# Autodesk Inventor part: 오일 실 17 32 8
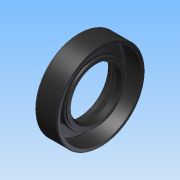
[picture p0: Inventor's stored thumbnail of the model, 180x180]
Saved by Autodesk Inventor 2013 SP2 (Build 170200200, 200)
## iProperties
Created: 2025-05
Part Number: 오일 실 17 32 8
Material: Generic
Document SubType Name: Modeling
Designer: a
Density: 1 g/cm^3
Author: a
변환 표준: STEP AP214IS
전처리기: Build: 200, Release: 2013 SP2 Update 6 - Date: Thu 07/17/2014
전송 단위: 밀리미터
불확실성: 0.01
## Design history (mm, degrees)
node "오일 실 17 32 81"
body "Solid1"
node "기준1"
